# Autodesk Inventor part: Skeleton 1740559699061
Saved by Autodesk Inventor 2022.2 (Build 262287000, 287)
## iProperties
_SkeletonDoc: Frame Skeleton File
_Version: 15.0.0
Created: 2025-02
Part Number: Skeleton 1740559699061
Material: Generico
Document SubType Name: Modeling
Designer: 18907419
Density: 1 g/cm^3
Appearance: Default
Author: 18907419
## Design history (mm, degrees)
sketch "Scheletro di riferimento"
